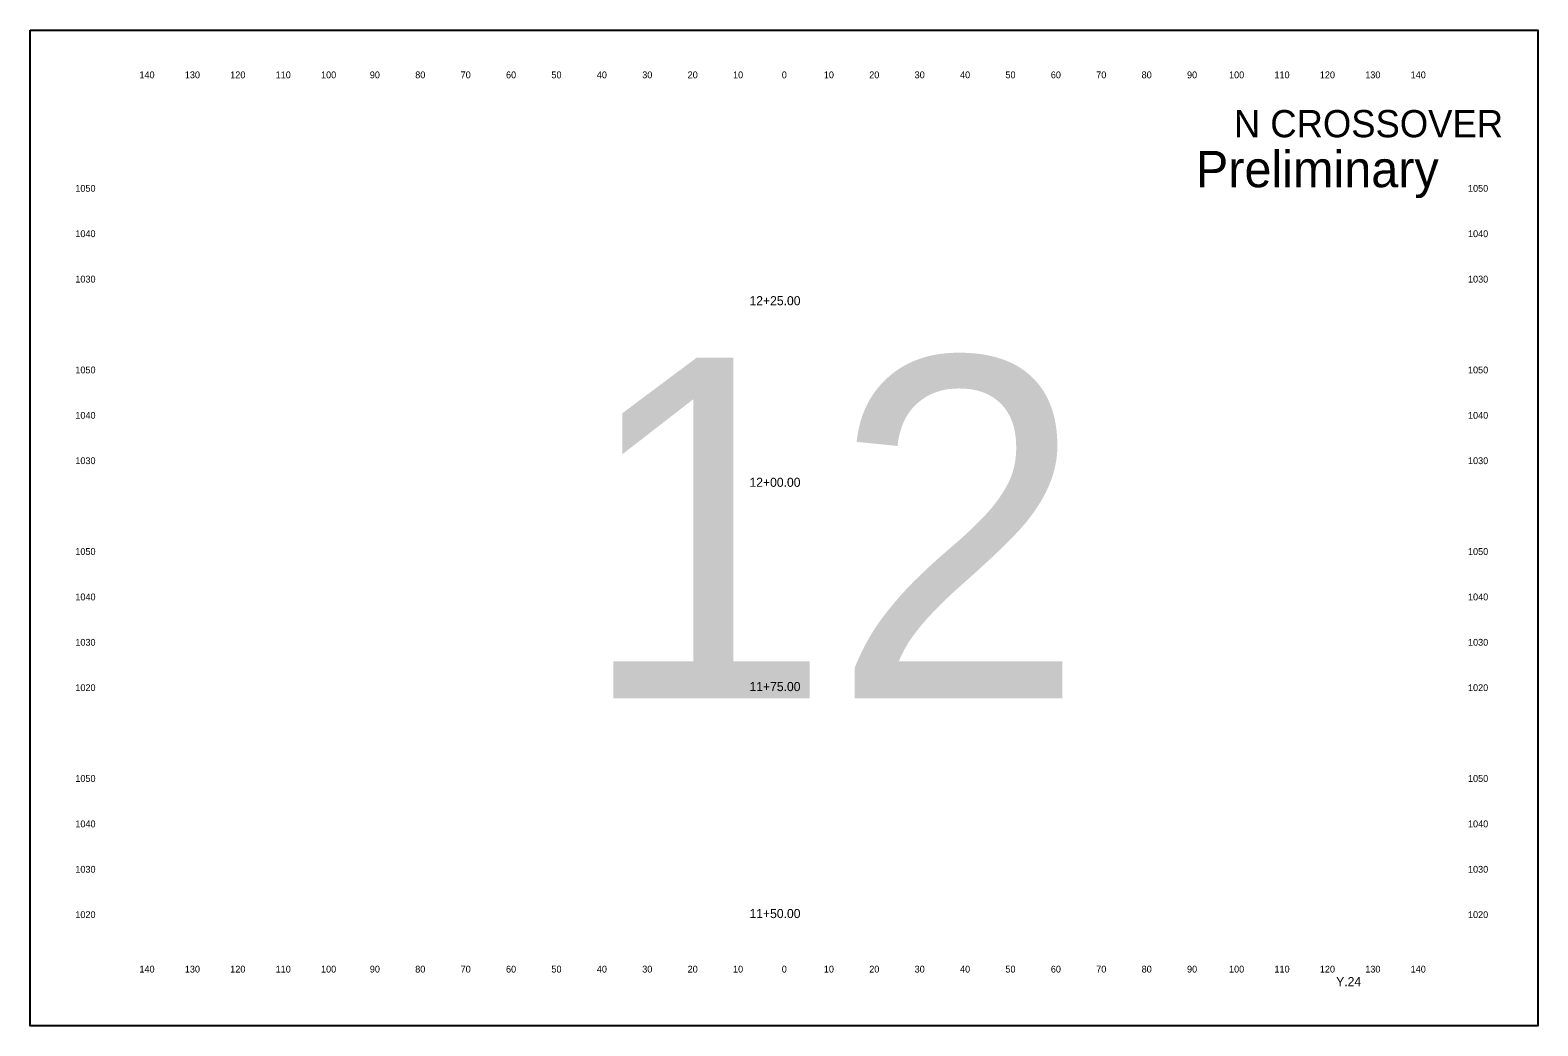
# Model space of a CAD drawing. Extents: x 10123 to 14767, y 9730 to 9950.
# Drawn here: x 14083.2 to 14415.3, y 9730.3 to 9949.6 of the extents above; entities that cross this region are included whole.
import ezdxf

# ---------------------------------------------------------------- set-up
doc = ezdxf.new("R2010")
doc.units = 0
for name, color, linetype in [('dsnTextCpn', 7, 'Continuous'), ('dsnTextCpnTitleSheetLocDesc', 7, 'Continuous'), ('dsnTextCpnTitleSheetPIN', 7, 'Continuous'), ('dsnTextCpnTitleSheetWorkType', 7, 'Continuous')]:
    doc.layers.add(name, color=color, linetype=linetype)

msp = doc.modelspace()

# ---------------------------------------------------------------- linework, layer by layer
at = {"layer": 'dsnTextCpnTitleSheetWorkType'}
msp.add_lwpolyline([(14083.21, 9949.6), (14415.29, 9949.6), (14415.29, 9730.26), (14083.21, 9730.26)], close=True, dxfattribs=at)

# ---------------------------------------------------------------- texts
at = {"layer": 'dsnTextCpn'}
for s, height, p in [('140', 1.5, (14107.27, 9939)), ('130', 1.5, (14117.27, 9939)), ('120', 1.5, (14127.27, 9939)), ('110', 1.5, (14137.27, 9939)), ('100', 1.5, (14147.27, 9939)), ('90', 1.5, (14158.02, 9939)), ('80', 1.5, (14168.02, 9939)), ('70', 1.5, (14178.02, 9939)), ('60', 1.5, (14188.02, 9939)), ('50', 1.5, (14198.02, 9939)), ('40', 1.5, (14208.02, 9939)), ('30', 1.5, (14218.02, 9939)), ('20', 1.5, (14228.02, 9939)), ('10', 1.5, (14238.02, 9939)), ('0', 1.5, (14248.76, 9939)), ('0', 1.5, (14248.76, 9939)), ('10', 1.5, (14258.02, 9939)), ('20', 1.5, (14268.02, 9939)), ('30', 1.5, (14278.02, 9939)), ('40', 1.5, (14288.02, 9939)), ('50', 1.5, (14298.02, 9939)), ('60', 1.5, (14308.02, 9939)), ('70', 1.5, (14318.02, 9939)), ('80', 1.5, (14328.02, 9939)), ('90', 1.5, (14338.02, 9939)), ('100', 1.5, (14347.27, 9939)), ('110', 1.5, (14357.27, 9939)), ('120', 1.5, (14367.27, 9939)), ('130', 1.5, (14377.27, 9939)), ('140', 1.5, (14387.27, 9939)), ('N CROSSOVER', 6, (14348.34, 9926)), ('1050', 1.5, (14093.15, 9914)), ('1050', 1.5, (14399.9, 9914)), ('1040', 1.5, (14093.15, 9904)), ('1040', 1.5, (14399.9, 9904)), ('1030', 1.5, (14093.15, 9894)), ('1030', 1.5, (14399.9, 9894)), ('12+25.00', 2, (14241.65, 9889)), ('1050', 1.5, (14093.15, 9874)), ('1050', 1.5, (14399.9, 9874)), ('1040', 1.5, (14093.15, 9864)), ('1040', 1.5, (14399.9, 9864)), ('1030', 1.5, (14093.15, 9854)), ('1030', 1.5, (14399.9, 9854)), ('12+00.00', 2, (14241.65, 9849)), ('1050', 1.5, (14093.15, 9834)), ('1050', 1.5, (14399.9, 9834)), ('1040', 1.5, (14093.15, 9824)), ('1040', 1.5, (14399.9, 9824)), ('1030', 1.5, (14093.15, 9814)), ('1030', 1.5, (14399.9, 9814)), ('1020', 1.5, (14093.15, 9804)), ('11+75.00', 2, (14241.65, 9804)), ('1020', 1.5, (14399.9, 9804)), ('1050', 1.5, (14093.15, 9784)), ('1050', 1.5, (14399.9, 9784)), ('1040', 1.5, (14093.15, 9774)), ('1040', 1.5, (14399.9, 9774)), ('1030', 1.5, (14093.15, 9764)), ('1030', 1.5, (14399.9, 9764)), ('1020', 1.5, (14093.15, 9754)), ('11+50.00', 2, (14241.65, 9754)), ('1020', 1.5, (14399.9, 9754)), ('140', 1.5, (14107.27, 9742)), ('130', 1.5, (14117.27, 9742)), ('120', 1.5, (14127.27, 9742)), ('110', 1.5, (14137.27, 9742)), ('100', 1.5, (14147.27, 9742)), ('90', 1.5, (14158.02, 9742)), ('80', 1.5, (14168.02, 9742)), ('70', 1.5, (14178.02, 9742)), ('60', 1.5, (14188.02, 9742)), ('50', 1.5, (14198.02, 9742)), ('40', 1.5, (14208.02, 9742)), ('30', 1.5, (14218.02, 9742)), ('20', 1.5, (14228.02, 9742)), ('10', 1.5, (14238.02, 9742)), ('0', 1.5, (14248.76, 9742)), ('0', 1.5, (14248.76, 9742)), ('10', 1.5, (14258.02, 9742)), ('20', 1.5, (14268.02, 9742)), ('30', 1.5, (14278.02, 9742)), ('40', 1.5, (14288.02, 9742)), ('50', 1.5, (14298.02, 9742)), ('60', 1.5, (14308.02, 9742)), ('70', 1.5, (14318.02, 9742)), ('80', 1.5, (14328.02, 9742)), ('90', 1.5, (14338.02, 9742)), ('100', 1.5, (14347.27, 9742)), ('110', 1.5, (14357.27, 9742)), ('120', 1.5, (14367.27, 9742)), ('130', 1.5, (14377.27, 9742)), ('140', 1.5, (14387.27, 9742))]:
    msp.add_text(s, height=height, dxfattribs=at).set_placement(p)
at = {"layer": 'dsnTextCpnTitleSheetLocDesc'}
msp.add_text('Preliminary', height=8, dxfattribs=at).set_placement((14339.97, 9915))
at = {"layer": 'dsnTextCpnTitleSheetPIN'}
msp.add_text('Y.24', height=2, dxfattribs=at).set_placement((14370.87, 9739))
at = {"layer": 'dsnTextCpnTitleSheetWorkType'}
msp.add_text('12', height=75, dxfattribs=at).set_placement((14204.03, 9802.43))

doc.saveas('drawing.dxf')
